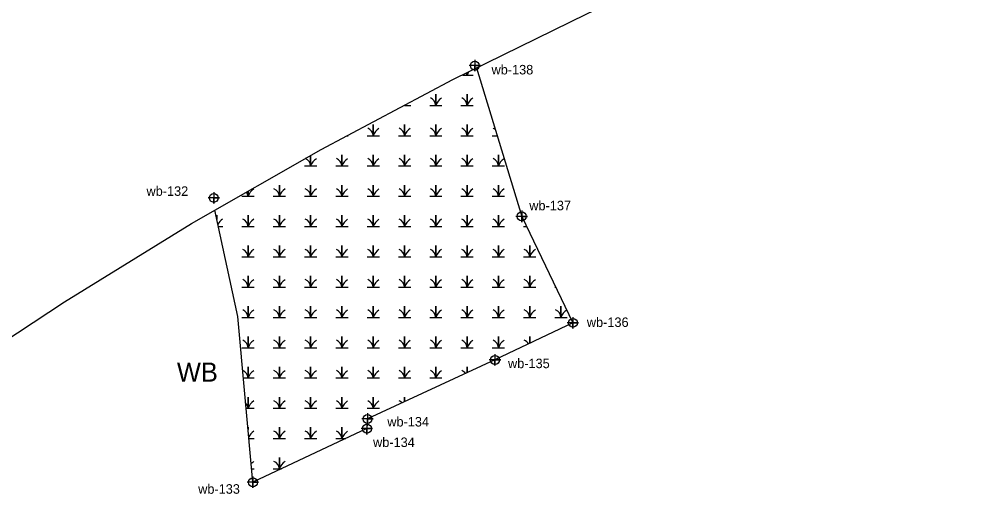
# Model space of a CAD drawing. Extents: x 2379288 to 2381905, y 330670 to 333511.
# Drawn here: x 2380893 to 2381399, y 332993 to 333252 of the extents above; entities that cross this region are included whole.
import ezdxf

# ---------------------------------------------------------------- set-up
doc = ezdxf.new("R2010")
doc.units = 0
for name, color, linetype in [('Default', 7, 'Continuous'), ('Exist Environmental Wetland Boundary', 7, 'Continuous'), ('Exist Environmental Wetland Boundary Cogo Number', 7, 'Continuous'), ('Exist Environmental Wetland Boundary Cogo Point CELL', 7, 'Continuous'), ('Exist Environmental Wetland Boundary Text', 7, 'Continuous'), ('Exist Hydro Swamp or Marsh', 7, 'Continuous')]:
    doc.layers.add(name, color=color, linetype=linetype)

msp = doc.modelspace()

# ---------------------------------------------------------------- linework, layer by layer
at = {"layer": 'Default'}
msp.add_lwpolyline([(2380850.96, 333060.51), (2380916.47, 333103.65), (2380983.3, 333144.71), (2381051.4, 333183.64), (2381120.69, 333220.4), (2381191.11, 333254.95), (2381734.22, 333510.92), (2381904.75, 333149.09), (2381361.64, 332893.12), (2381295.86, 332860.7), (2381231.27, 332825.99), (2381167.94, 332789.02), (2381105.95, 332749.86), (2381045.37, 332708.54), (2380986.28, 332665.11), (2380928.76, 332619.64), (2380872.86, 332572.17)], dxfattribs=at)
at = {"layer": 'Exist Environmental Wetland Boundary'}
msp.add_lwpolyline([(2381133.13, 333226.5), (2381156.86, 333148.5), (2381183.78, 333092.54), (2381142.81, 333073.06), (2381075.78, 333042.02), (2381075.47, 333036.92), (2381015.55, 333008.74), (2381007.56, 333095.8), (2380995.52, 333151.69)], dxfattribs=at)
at = {"layer": 'Exist Environmental Wetland Boundary Cogo Point CELL'}
for points in [[(2381132.2, 333230.75), (2381132.2, 333224.75), (2381132.2, 333227.75), (2381135.2, 333227.75), (2381129.2, 333227.75)], [(2380994.97, 333161.21), (2380994.97, 333155.21), (2380994.97, 333158.21), (2380997.97, 333158.21), (2380991.97, 333158.21)], [(2381156.85, 333151.5), (2381156.85, 333145.5), (2381156.85, 333148.5), (2381159.85, 333148.5), (2381153.85, 333148.5)], [(2381183.78, 333095.54), (2381183.78, 333089.54), (2381183.78, 333092.54), (2381186.78, 333092.54), (2381180.78, 333092.54)], [(2381142.81, 333076.06), (2381142.81, 333070.06), (2381142.81, 333073.06), (2381145.81, 333073.06), (2381139.81, 333073.06)], [(2381075.78, 333045.02), (2381075.78, 333039.02), (2381075.78, 333042.02), (2381078.78, 333042.02), (2381072.78, 333042.02)], [(2381075.47, 333039.92), (2381075.47, 333033.92), (2381075.47, 333036.92), (2381078.47, 333036.92), (2381072.47, 333036.92)], [(2381015.55, 333011.74), (2381015.55, 333005.74), (2381015.55, 333008.74), (2381018.55, 333008.74), (2381012.55, 333008.74)]]:
    msp.add_lwpolyline(points, dxfattribs=at)
for centre in [(2381132.2, 333227.75), (2380994.97, 333158.21), (2381156.85, 333148.5), (2381183.78, 333092.54), (2381142.81, 333073.06), (2381075.78, 333042.02), (2381075.47, 333036.92), (2381015.55, 333008.74)]:
    msp.add_circle(centre, 2.34, dxfattribs=at)
at = {"layer": 'Exist Hydro Swamp or Marsh'}
for p, q in [((2381065.08, 333190.9), (2381065.58, 333190.9)), ((2381141.38, 333190.9), (2381143.96, 333190.9)), ((2380997.36, 333143.14), (2380999.77, 333143.14)), ((2381157.83, 333143.14), (2381159.43, 333143.14)), ((2381174.28, 333111.31), (2381174.75, 333111.31)), ((2381013.44, 333031.72), (2381016.22, 333031.72)), ((2381014.9, 333015.8), (2381016.22, 333015.8))]:
    msp.add_line(p, q, dxfattribs=at)
for points in [[(2381125.88, 333222.73), (2381128.15, 333222.73), (2381128.15, 333223.92)], [(2381128.15, 333223.92), (2381128.15, 333222.73), (2381131.38, 333222.73)], [(2381108.48, 333206.81), (2381111.7, 333206.81), (2381111.7, 333212.73), (2381111.7, 333206.81), (2381114.93, 333206.81)], [(2381124.93, 333206.81), (2381128.15, 333206.81), (2381128.15, 333212.73), (2381128.15, 333206.81), (2381131.38, 333206.81)], [(2381095.24, 333206.81), (2381095.25, 333206.81), (2381095.25, 333206.82)], [(2381095.25, 333206.82), (2381095.25, 333206.81), (2381098.48, 333206.81)], [(2381075.58, 333190.9), (2381078.8, 333190.9), (2381078.8, 333196.81), (2381078.8, 333190.9), (2381082.03, 333190.9)], [(2381092.03, 333190.9), (2381095.25, 333190.9), (2381095.25, 333196.81), (2381095.25, 333190.9), (2381098.48, 333190.9)], [(2381108.48, 333190.9), (2381111.7, 333190.9), (2381111.7, 333196.81), (2381111.7, 333190.9), (2381114.93, 333190.9)], [(2381124.93, 333190.9), (2381128.15, 333190.9), (2381128.15, 333196.81), (2381128.15, 333190.9), (2381131.38, 333190.9)], [(2381042.67, 333174.98), (2381045.9, 333174.98), (2381045.9, 333180.49)], [(2381045.9, 333180.49), (2381045.9, 333174.98), (2381049.12, 333174.98)], [(2381059.12, 333174.98), (2381062.35, 333174.98), (2381062.35, 333180.9), (2381062.35, 333174.98), (2381065.58, 333174.98)], [(2381075.58, 333174.98), (2381078.8, 333174.98), (2381078.8, 333180.9), (2381078.8, 333174.98), (2381082.03, 333174.98)], [(2381092.03, 333174.98), (2381095.25, 333174.98), (2381095.25, 333180.9), (2381095.25, 333174.98), (2381098.48, 333174.98)], [(2381108.48, 333174.98), (2381111.7, 333174.98), (2381111.7, 333180.9), (2381111.7, 333174.98), (2381114.93, 333174.98)], [(2381124.93, 333174.98), (2381128.15, 333174.98), (2381128.15, 333180.9), (2381128.15, 333174.98), (2381131.38, 333174.98)], [(2381141.38, 333174.98), (2381144.61, 333174.98), (2381144.61, 333180.9), (2381144.61, 333174.98), (2381147.83, 333174.98)], [(2381026.22, 333159.06), (2381029.45, 333159.06), (2381029.45, 333164.98), (2381029.45, 333159.06), (2381032.67, 333159.06)], [(2381042.67, 333159.06), (2381045.9, 333159.06), (2381045.9, 333164.98), (2381045.9, 333159.06), (2381049.12, 333159.06)], [(2381059.12, 333159.06), (2381062.35, 333159.06), (2381062.35, 333164.98), (2381062.35, 333159.06), (2381065.58, 333159.06)], [(2381075.58, 333159.06), (2381078.8, 333159.06), (2381078.8, 333164.98), (2381078.8, 333159.06), (2381082.03, 333159.06)], [(2381092.03, 333159.06), (2381095.25, 333159.06), (2381095.25, 333164.98), (2381095.25, 333159.06), (2381098.48, 333159.06)], [(2381108.48, 333159.06), (2381111.7, 333159.06), (2381111.7, 333164.98), (2381111.7, 333159.06), (2381114.93, 333159.06)], [(2381124.93, 333159.06), (2381128.15, 333159.06), (2381128.15, 333164.98), (2381128.15, 333159.06), (2381131.38, 333159.06)], [(2381141.38, 333159.06), (2381144.61, 333159.06), (2381144.61, 333164.98), (2381144.61, 333159.06), (2381147.83, 333159.06)], [(2381009.77, 333159.06), (2381013, 333159.06), (2381013, 333161.68)], [(2381013, 333161.68), (2381013, 333159.06), (2381016.22, 333159.06)], [(2380996.54, 333146.92), (2380996.54, 333149.06), (2380996.54, 333146.92)], [(2381009.77, 333143.14), (2381013, 333143.14), (2381013, 333149.06), (2381013, 333143.14), (2381016.22, 333143.14)], [(2381026.22, 333143.14), (2381029.45, 333143.14), (2381029.45, 333149.06), (2381029.45, 333143.14), (2381032.67, 333143.14)], [(2381042.67, 333143.14), (2381045.9, 333143.14), (2381045.9, 333149.06), (2381045.9, 333143.14), (2381049.12, 333143.14)], [(2381059.12, 333143.14), (2381062.35, 333143.14), (2381062.35, 333149.06), (2381062.35, 333143.14), (2381065.58, 333143.14)], [(2381075.58, 333143.14), (2381078.8, 333143.14), (2381078.8, 333149.06), (2381078.8, 333143.14), (2381082.03, 333143.14)], [(2381092.03, 333143.14), (2381095.25, 333143.14), (2381095.25, 333149.06), (2381095.25, 333143.14), (2381098.48, 333143.14)], [(2381108.48, 333143.14), (2381111.7, 333143.14), (2381111.7, 333149.06), (2381111.7, 333143.14), (2381114.93, 333143.14)], [(2381124.93, 333143.14), (2381128.15, 333143.14), (2381128.15, 333149.06), (2381128.15, 333143.14), (2381131.38, 333143.14)], [(2381141.38, 333143.14), (2381144.61, 333143.14), (2381144.61, 333149.06), (2381144.61, 333143.14), (2381147.83, 333143.14)], [(2381009.77, 333127.23), (2381013, 333127.23), (2381013, 333133.14), (2381013, 333127.23), (2381016.22, 333127.23)], [(2381026.22, 333127.23), (2381029.45, 333127.23), (2381029.45, 333133.14), (2381029.45, 333127.23), (2381032.67, 333127.23)], [(2381042.67, 333127.23), (2381045.9, 333127.23), (2381045.9, 333133.14), (2381045.9, 333127.23), (2381049.12, 333127.23)], [(2381059.12, 333127.23), (2381062.35, 333127.23), (2381062.35, 333133.14), (2381062.35, 333127.23), (2381065.58, 333127.23)], [(2381075.58, 333127.23), (2381078.8, 333127.23), (2381078.8, 333133.14), (2381078.8, 333127.23), (2381082.03, 333127.23)], [(2381092.03, 333127.23), (2381095.25, 333127.23), (2381095.25, 333133.14), (2381095.25, 333127.23), (2381098.48, 333127.23)], [(2381108.48, 333127.23), (2381111.7, 333127.23), (2381111.7, 333133.14), (2381111.7, 333127.23), (2381114.93, 333127.23)], [(2381124.93, 333127.23), (2381128.15, 333127.23), (2381128.15, 333133.14), (2381128.15, 333127.23), (2381131.38, 333127.23)], [(2381141.38, 333127.23), (2381144.61, 333127.23), (2381144.61, 333133.14), (2381144.61, 333127.23), (2381147.83, 333127.23)], [(2381157.83, 333127.23), (2381161.06, 333127.23), (2381161.06, 333133.14), (2381161.06, 333127.23), (2381164.28, 333127.23)], [(2381009.77, 333111.31), (2381013, 333111.31), (2381013, 333117.23), (2381013, 333111.31), (2381016.22, 333111.31)], [(2381026.22, 333111.31), (2381029.45, 333111.31), (2381029.45, 333117.23), (2381029.45, 333111.31), (2381032.67, 333111.31)], [(2381042.67, 333111.31), (2381045.9, 333111.31), (2381045.9, 333117.23), (2381045.9, 333111.31), (2381049.12, 333111.31)], [(2381059.12, 333111.31), (2381062.35, 333111.31), (2381062.35, 333117.23), (2381062.35, 333111.31), (2381065.58, 333111.31)], [(2381075.58, 333111.31), (2381078.8, 333111.31), (2381078.8, 333117.23), (2381078.8, 333111.31), (2381082.03, 333111.31)], [(2381092.03, 333111.31), (2381095.25, 333111.31), (2381095.25, 333117.23), (2381095.25, 333111.31), (2381098.48, 333111.31)], [(2381108.48, 333111.31), (2381111.7, 333111.31), (2381111.7, 333117.23), (2381111.7, 333111.31), (2381114.93, 333111.31)], [(2381124.93, 333111.31), (2381128.15, 333111.31), (2381128.15, 333117.23), (2381128.15, 333111.31), (2381131.38, 333111.31)], [(2381141.38, 333111.31), (2381144.61, 333111.31), (2381144.61, 333117.23), (2381144.61, 333111.31), (2381147.83, 333111.31)], [(2381157.83, 333111.31), (2381161.06, 333111.31), (2381161.06, 333117.23), (2381161.06, 333111.31), (2381164.28, 333111.31)], [(2381009.77, 333095.39), (2381013, 333095.39), (2381013, 333101.31), (2381013, 333095.39), (2381016.22, 333095.39)], [(2381026.22, 333095.39), (2381029.45, 333095.39), (2381029.45, 333101.31), (2381029.45, 333095.39), (2381032.67, 333095.39)], [(2381042.67, 333095.39), (2381045.9, 333095.39), (2381045.9, 333101.31), (2381045.9, 333095.39), (2381049.12, 333095.39)], [(2381059.12, 333095.39), (2381062.35, 333095.39), (2381062.35, 333101.31), (2381062.35, 333095.39), (2381065.58, 333095.39)], [(2381075.58, 333095.39), (2381078.8, 333095.39), (2381078.8, 333101.31), (2381078.8, 333095.39), (2381082.03, 333095.39)], [(2381092.03, 333095.39), (2381095.25, 333095.39), (2381095.25, 333101.31), (2381095.25, 333095.39), (2381098.48, 333095.39)], [(2381108.48, 333095.39), (2381111.7, 333095.39), (2381111.7, 333101.31), (2381111.7, 333095.39), (2381114.93, 333095.39)], [(2381124.93, 333095.39), (2381128.15, 333095.39), (2381128.15, 333101.31), (2381128.15, 333095.39), (2381131.38, 333095.39)], [(2381141.38, 333095.39), (2381144.61, 333095.39), (2381144.61, 333101.31), (2381144.61, 333095.39), (2381147.83, 333095.39)], [(2381157.83, 333095.39), (2381161.06, 333095.39), (2381161.06, 333101.31), (2381161.06, 333095.39), (2381164.28, 333095.39)], [(2381174.28, 333095.39), (2381177.51, 333095.39), (2381177.51, 333101.31), (2381177.51, 333095.39), (2381180.73, 333095.39)], [(2381009.77, 333079.47), (2381013, 333079.47), (2381013, 333085.39), (2381013, 333079.47), (2381016.22, 333079.47)], [(2381026.22, 333079.47), (2381029.45, 333079.47), (2381029.45, 333085.39), (2381029.45, 333079.47), (2381032.67, 333079.47)], [(2381042.67, 333079.47), (2381045.9, 333079.47), (2381045.9, 333085.39), (2381045.9, 333079.47), (2381049.12, 333079.47)], [(2381059.12, 333079.47), (2381062.35, 333079.47), (2381062.35, 333085.39), (2381062.35, 333079.47), (2381065.58, 333079.47)], [(2381075.58, 333079.47), (2381078.8, 333079.47), (2381078.8, 333085.39), (2381078.8, 333079.47), (2381082.03, 333079.47)], [(2381092.03, 333079.47), (2381095.25, 333079.47), (2381095.25, 333085.39), (2381095.25, 333079.47), (2381098.48, 333079.47)], [(2381108.48, 333079.47), (2381111.7, 333079.47), (2381111.7, 333085.39), (2381111.7, 333079.47), (2381114.93, 333079.47)], [(2381124.93, 333079.47), (2381128.15, 333079.47), (2381128.15, 333085.39), (2381128.15, 333079.47), (2381131.38, 333079.47)], [(2381141.38, 333079.47), (2381144.61, 333079.47), (2381144.61, 333085.39), (2381144.61, 333079.47), (2381147.83, 333079.47)], [(2381161.06, 333081.74), (2381161.06, 333085.39), (2381161.06, 333081.74)], [(2381010.52, 333063.56), (2381013, 333063.56), (2381013, 333069.47), (2381013, 333063.56), (2381016.22, 333063.56)], [(2381026.22, 333063.56), (2381029.45, 333063.56), (2381029.45, 333069.47), (2381029.45, 333063.56), (2381032.67, 333063.56)], [(2381042.67, 333063.56), (2381045.9, 333063.56), (2381045.9, 333069.47), (2381045.9, 333063.56), (2381049.12, 333063.56)], [(2381059.12, 333063.56), (2381062.35, 333063.56), (2381062.35, 333069.47), (2381062.35, 333063.56), (2381065.58, 333063.56)], [(2381075.58, 333063.56), (2381078.8, 333063.56), (2381078.8, 333069.47), (2381078.8, 333063.56), (2381082.03, 333063.56)], [(2381092.03, 333063.56), (2381095.25, 333063.56), (2381095.25, 333069.47), (2381095.25, 333063.56), (2381098.48, 333063.56)], [(2381108.48, 333063.56), (2381111.7, 333063.56), (2381111.7, 333069.47), (2381111.7, 333063.56), (2381114.93, 333063.56)], [(2381128.15, 333066.28), (2381128.15, 333069.47), (2381128.15, 333066.28)], [(2381011.98, 333047.64), (2381013, 333047.64), (2381013, 333053.56), (2381013, 333047.64), (2381016.22, 333047.64)], [(2381026.22, 333047.64), (2381029.45, 333047.64), (2381029.45, 333053.56), (2381029.45, 333047.64), (2381032.67, 333047.64)], [(2381042.67, 333047.64), (2381045.9, 333047.64), (2381045.9, 333053.56), (2381045.9, 333047.64), (2381049.12, 333047.64)], [(2381059.12, 333047.64), (2381062.35, 333047.64), (2381062.35, 333053.56), (2381062.35, 333047.64), (2381065.58, 333047.64)], [(2381075.58, 333047.64), (2381078.8, 333047.64), (2381078.8, 333053.56), (2381078.8, 333047.64), (2381082.03, 333047.64)], [(2381095.25, 333051.04), (2381095.25, 333053.56), (2381095.25, 333051.04)], [(2381013, 333036.55), (2381013, 333037.64), (2381013, 333036.55)], [(2381026.22, 333031.72), (2381029.45, 333031.72), (2381029.45, 333037.64), (2381029.45, 333031.72), (2381032.67, 333031.72)], [(2381042.67, 333031.72), (2381045.9, 333031.72), (2381045.9, 333037.64), (2381045.9, 333031.72), (2381049.12, 333031.72)], [(2381059.12, 333031.72), (2381062.35, 333031.72), (2381062.35, 333037.64), (2381062.35, 333031.72), (2381064.42, 333031.72)], [(2381026.22, 333015.8), (2381029.45, 333015.8), (2381029.45, 333021.72), (2381029.45, 333015.8), (2381030.57, 333015.8)]]:
    msp.add_lwpolyline(points, dxfattribs=at)
for centre, radius, start, end in [((2381123.55, 333222.4), 4.61, 4.1403, 17.7732), ((2381135, 333220.46), 7.21, 147.8075, 161.6222), ((2381107.1, 333206.48), 4.61, 4.1403, 67.535), ((2381118.54, 333204.54), 7.21, 122.1274, 161.6222), ((2381123.55, 333206.48), 4.61, 4.1403, 67.535), ((2381135, 333204.54), 7.21, 122.1274, 161.6222), ((2381102.09, 333204.54), 7.21, 161.5794, 161.6222), ((2381090.65, 333206.48), 4.61, 4.1403, 4.1911), ((2381074.2, 333190.56), 4.61, 4.1403, 67.535), ((2381085.64, 333188.62), 7.21, 122.1274, 161.6222), ((2381090.65, 333190.56), 4.61, 4.1403, 67.535), ((2381102.09, 333188.62), 7.21, 122.1274, 161.6222), ((2381107.1, 333190.56), 4.61, 4.1403, 67.535), ((2381118.54, 333188.62), 7.21, 122.1274, 161.6222), ((2381123.55, 333190.56), 4.61, 4.1403, 67.535), ((2381135, 333188.62), 7.21, 122.1274, 161.6222), ((2381140.01, 333190.56), 4.61, 49.6802, 67.535), ((2381041.3, 333174.65), 4.61, 4.1403, 67.0205), ((2381052.74, 333172.71), 7.21, 122.1274, 161.6222), ((2381057.75, 333174.65), 4.61, 4.1403, 67.535), ((2381069.19, 333172.71), 7.21, 122.1274, 161.6222), ((2381074.2, 333174.65), 4.61, 4.1403, 67.535), ((2381085.64, 333172.71), 7.21, 122.1274, 161.6222), ((2381090.65, 333174.65), 4.61, 4.1403, 67.535), ((2381102.09, 333172.71), 7.21, 122.1274, 161.6222), ((2381107.1, 333174.65), 4.61, 4.1403, 67.535), ((2381118.54, 333172.71), 7.21, 122.1274, 161.6222), ((2381123.55, 333174.65), 4.61, 4.1403, 67.535), ((2381135, 333172.71), 7.21, 122.1274, 161.6222), ((2381140.01, 333174.65), 4.61, 4.1403, 67.535), ((2381151.45, 333172.71), 7.21, 122.1274, 161.6222), ((2381019.84, 333156.79), 7.21, 122.1274, 161.6222), ((2381024.85, 333158.73), 4.61, 4.1403, 67.535), ((2381036.29, 333156.79), 7.21, 122.1274, 161.6222), ((2381041.3, 333158.73), 4.61, 4.1403, 67.535), ((2381052.74, 333156.79), 7.21, 122.1274, 161.6222), ((2381057.75, 333158.73), 4.61, 4.1403, 67.535), ((2381069.19, 333156.79), 7.21, 122.1274, 161.6222), ((2381074.2, 333158.73), 4.61, 4.1403, 67.535), ((2381085.64, 333156.79), 7.21, 122.1274, 161.6222), ((2381090.65, 333158.73), 4.61, 4.1403, 67.535), ((2381102.09, 333156.79), 7.21, 122.1274, 161.6222), ((2381107.1, 333158.73), 4.61, 4.1403, 67.535), ((2381118.54, 333156.79), 7.21, 122.1274, 161.6222), ((2381123.55, 333158.73), 4.61, 4.1403, 67.535), ((2381135, 333156.79), 7.21, 122.1274, 161.6222), ((2381140.01, 333158.73), 4.61, 4.1403, 67.535), ((2381151.45, 333156.79), 7.21, 122.1274, 161.6222), ((2381008.4, 333158.73), 4.61, 4.1403, 33.2737), ((2381003.39, 333140.87), 7.21, 122.1274, 150.8324), ((2381008.4, 333142.81), 4.61, 4.1403, 67.535), ((2381019.84, 333140.87), 7.21, 122.1274, 161.6222), ((2381024.85, 333142.81), 4.61, 4.1403, 67.535), ((2381036.29, 333140.87), 7.21, 122.1274, 161.6222), ((2381041.3, 333142.81), 4.61, 4.1403, 67.535), ((2381052.74, 333140.87), 7.21, 122.1274, 161.6222), ((2381057.75, 333142.81), 4.61, 4.1403, 67.535), ((2381069.19, 333140.87), 7.21, 122.1274, 161.6222), ((2381074.2, 333142.81), 4.61, 4.1403, 67.535), ((2381085.64, 333140.87), 7.21, 122.1274, 161.6222), ((2381090.65, 333142.81), 4.61, 4.1403, 67.535), ((2381102.09, 333140.87), 7.21, 122.1274, 161.6222), ((2381107.1, 333142.81), 4.61, 4.1403, 67.535), ((2381118.54, 333140.87), 7.21, 122.1274, 161.6222), ((2381123.55, 333142.81), 4.61, 4.1403, 67.535), ((2381135, 333140.87), 7.21, 122.1274, 161.6222), ((2381140.01, 333142.81), 4.61, 4.1403, 67.535), ((2381151.45, 333140.87), 7.21, 122.1274, 161.6222), ((2381008.4, 333126.89), 4.61, 4.1403, 67.535), ((2381019.84, 333124.95), 7.21, 122.1274, 161.6222), ((2381024.85, 333126.89), 4.61, 4.1403, 67.535), ((2381036.29, 333124.95), 7.21, 122.1274, 161.6222), ((2381041.3, 333126.89), 4.61, 4.1403, 67.535), ((2381052.74, 333124.95), 7.21, 122.1274, 161.6222), ((2381057.75, 333126.89), 4.61, 4.1403, 67.535), ((2381069.19, 333124.95), 7.21, 122.1274, 161.6222), ((2381074.2, 333126.89), 4.61, 4.1403, 67.535), ((2381085.64, 333124.95), 7.21, 122.1274, 161.6222), ((2381090.65, 333126.89), 4.61, 4.1403, 67.535), ((2381102.09, 333124.95), 7.21, 122.1274, 161.6222), ((2381107.1, 333126.89), 4.61, 4.1403, 67.535), ((2381118.54, 333124.95), 7.21, 122.1274, 161.6222), ((2381123.55, 333126.89), 4.61, 4.1403, 67.535), ((2381135, 333124.95), 7.21, 122.1274, 161.6222), ((2381140.01, 333126.89), 4.61, 4.1403, 67.535), ((2381151.45, 333124.95), 7.21, 122.1274, 161.6222), ((2381156.46, 333126.89), 4.61, 4.1403, 67.535), ((2381167.9, 333124.95), 7.21, 122.1274, 161.6222), ((2381008.4, 333110.98), 4.61, 4.1403, 67.535), ((2381019.84, 333109.04), 7.21, 122.1274, 161.6222), ((2381024.85, 333110.98), 4.61, 4.1403, 67.535), ((2381036.29, 333109.04), 7.21, 122.1274, 161.6222), ((2381041.3, 333110.98), 4.61, 4.1403, 67.535), ((2381052.74, 333109.04), 7.21, 122.1274, 161.6222), ((2381057.75, 333110.98), 4.61, 4.1403, 67.535), ((2381069.19, 333109.04), 7.21, 122.1274, 161.6222), ((2381074.2, 333110.98), 4.61, 4.1403, 67.535), ((2381085.64, 333109.04), 7.21, 122.1274, 161.6222), ((2381090.65, 333110.98), 4.61, 4.1403, 67.535), ((2381102.09, 333109.04), 7.21, 122.1274, 161.6222), ((2381107.1, 333110.98), 4.61, 4.1403, 67.535), ((2381118.54, 333109.04), 7.21, 122.1274, 161.6222), ((2381123.55, 333110.98), 4.61, 4.1403, 67.535), ((2381135, 333109.04), 7.21, 122.1274, 161.6222), ((2381140.01, 333110.98), 4.61, 4.1403, 67.535), ((2381151.45, 333109.04), 7.21, 122.1274, 161.6222), ((2381156.46, 333110.98), 4.61, 4.1403, 67.535), ((2381167.9, 333109.04), 7.21, 122.1274, 161.6222), ((2381008.4, 333095.06), 4.61, 4.1403, 67.535), ((2381019.84, 333093.12), 7.21, 122.1274, 161.6222), ((2381024.85, 333095.06), 4.61, 4.1403, 67.535), ((2381036.29, 333093.12), 7.21, 122.1274, 161.6222), ((2381041.3, 333095.06), 4.61, 4.1403, 67.535), ((2381052.74, 333093.12), 7.21, 122.1274, 161.6222), ((2381057.75, 333095.06), 4.61, 4.1403, 67.535), ((2381069.19, 333093.12), 7.21, 122.1274, 161.6222), ((2381074.2, 333095.06), 4.61, 4.1403, 67.535), ((2381085.64, 333093.12), 7.21, 122.1274, 161.6222), ((2381090.65, 333095.06), 4.61, 4.1403, 67.535), ((2381102.09, 333093.12), 7.21, 122.1274, 161.6222), ((2381107.1, 333095.06), 4.61, 4.1403, 67.535), ((2381118.54, 333093.12), 7.21, 122.1274, 161.6222), ((2381123.55, 333095.06), 4.61, 4.1403, 67.535), ((2381135, 333093.12), 7.21, 122.1274, 161.6222), ((2381140.01, 333095.06), 4.61, 4.1403, 67.535), ((2381151.45, 333093.12), 7.21, 122.1274, 161.6222), ((2381156.46, 333095.06), 4.61, 4.1403, 67.535), ((2381167.9, 333093.12), 7.21, 122.1274, 161.6222), ((2381172.91, 333095.06), 4.61, 4.1403, 67.535), ((2381184.35, 333093.12), 7.21, 122.1274, 161.6222), ((2381008.4, 333079.14), 4.61, 4.1403, 67.535), ((2381019.84, 333077.2), 7.21, 122.1274, 161.6222), ((2381024.85, 333079.14), 4.61, 4.1403, 67.535), ((2381036.29, 333077.2), 7.21, 122.1274, 161.6222), ((2381041.3, 333079.14), 4.61, 4.1403, 67.535), ((2381052.74, 333077.2), 7.21, 122.1274, 161.6222), ((2381057.75, 333079.14), 4.61, 4.1403, 67.535), ((2381069.19, 333077.2), 7.21, 122.1274, 161.6222), ((2381074.2, 333079.14), 4.61, 4.1403, 67.535), ((2381085.64, 333077.2), 7.21, 122.1274, 161.6222), ((2381090.65, 333079.14), 4.61, 4.1403, 67.535), ((2381102.09, 333077.2), 7.21, 122.1274, 161.6222), ((2381107.1, 333079.14), 4.61, 4.1403, 67.535), ((2381118.54, 333077.2), 7.21, 122.1274, 161.6222), ((2381123.55, 333079.14), 4.61, 4.1403, 67.535), ((2381135, 333077.2), 7.21, 122.1274, 161.6222), ((2381140.01, 333079.14), 4.61, 4.1403, 67.535), ((2381151.45, 333077.2), 7.21, 122.1274, 161.6222), ((2381156.46, 333079.14), 4.61, 30.0428, 67.535), ((2381167.9, 333077.2), 7.21, 122.1274, 128.0225), ((2381008.4, 333063.22), 4.61, 4.1403, 67.5226), ((2381019.84, 333061.28), 7.21, 122.1274, 161.6222), ((2381024.85, 333063.22), 4.61, 4.1403, 67.535), ((2381036.29, 333061.28), 7.21, 122.1274, 161.6222), ((2381041.3, 333063.22), 4.61, 4.1403, 67.535), ((2381052.74, 333061.28), 7.21, 122.1274, 161.6222), ((2381057.75, 333063.22), 4.61, 4.1403, 67.535), ((2381069.19, 333061.28), 7.21, 122.1274, 161.6222), ((2381074.2, 333063.22), 4.61, 4.1403, 67.535), ((2381085.64, 333061.28), 7.21, 122.1274, 161.6222), ((2381090.65, 333063.22), 4.61, 4.1403, 67.535), ((2381102.09, 333061.28), 7.21, 122.1274, 161.6222), ((2381107.1, 333063.22), 4.61, 4.1403, 67.535), ((2381118.54, 333061.28), 7.21, 122.1274, 161.6222), ((2381123.55, 333063.22), 4.61, 35.317, 67.535), ((2381024.85, 333047.3), 4.61, 4.1403, 67.535), ((2381041.3, 333047.3), 4.61, 4.1403, 67.535), ((2381057.75, 333047.3), 4.61, 4.1403, 67.535), ((2381074.2, 333047.3), 4.61, 4.1403, 67.535), ((2381090.65, 333047.3), 4.61, 43.2193, 67.535), ((2381008.4, 333047.3), 4.61, 4.1403, 43.9523), ((2381019.84, 333045.36), 7.21, 122.1274, 161.6222), ((2381036.29, 333045.36), 7.21, 122.1274, 161.6222), ((2381052.74, 333045.36), 7.21, 122.1274, 161.6222), ((2381069.19, 333045.36), 7.21, 122.1274, 161.6222), ((2381085.64, 333045.36), 7.21, 122.1274, 161.6222), ((2381019.84, 333029.45), 7.21, 122.1274, 154.0034), ((2381024.85, 333031.39), 4.61, 4.1403, 67.535), ((2381036.29, 333029.45), 7.21, 122.1274, 161.6222), ((2381041.3, 333031.39), 4.61, 4.1403, 67.535), ((2381052.74, 333029.45), 7.21, 122.1274, 161.6222), ((2381057.75, 333031.39), 4.61, 4.1403, 67.535), ((2381069.19, 333029.45), 7.21, 122.1274, 161.6222), ((2381019.84, 333013.53), 7.21, 122.1274, 136.0368), ((2381024.85, 333015.47), 4.61, 4.1403, 67.535), ((2381036.29, 333013.53), 7.21, 122.1274, 161.6222)]:
    msp.add_arc(centre, radius, start, end, dxfattribs=at)

# ---------------------------------------------------------------- texts
at = {"layer": 'Exist Environmental Wetland Boundary Cogo Number'}
for s, p in [('wb-138', (2381141.01, 333223.09)), ('wb-132', (2380959.6, 333159.28)), ('wb-137', (2381160.84, 333151.68)), ('wb-136', (2381191.12, 333090.36)), ('wb-135', (2381149.66, 333068.72)), ('wb-134', (2381086.2, 333038.06)), ('wb-134', (2381078.71, 333027.27)), ('wb-133', (2380986.77, 333002.72))]:
    msp.add_text(s, height=5, dxfattribs=at).set_placement(p)
at = {"layer": 'Exist Environmental Wetland Boundary Text'}
msp.add_text('WB', height=10, dxfattribs=at).set_placement((2380975.58, 333061.66))

doc.saveas('drawing.dxf')
